// Mitsubishi GX Works2 project: 计数器   PLC: FX3U/FX3UC

PROGRAM MAIN
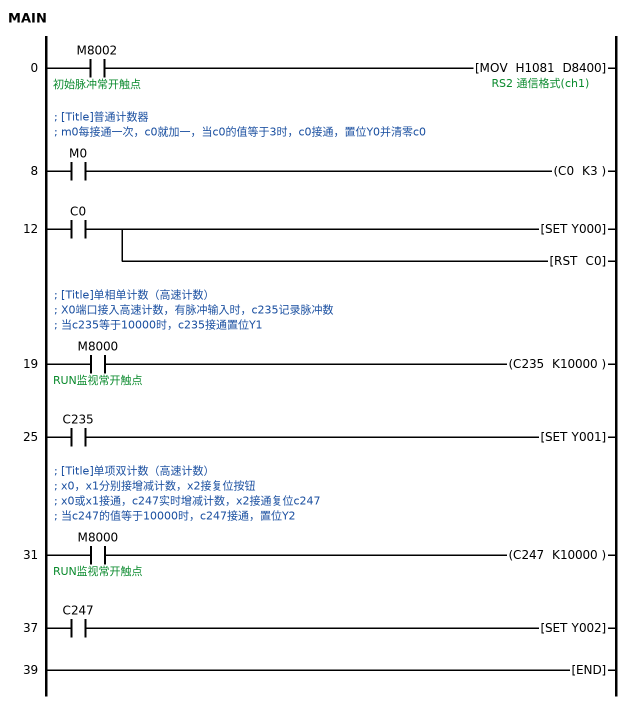
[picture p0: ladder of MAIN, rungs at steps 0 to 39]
0     LD      M8002  ; 初始脉冲常开触点
      MOV     H1081 D8400  ; RS2 通信格式(ch1)
; [Title]普通计数器
; m0每接通一次，c0就加一，当c0的值等于3时，c0接通，置位Y0并清零c0
8     LD      M0
      OUT     C0 K3
12    LD      C0
      SET     Y000
      RST     C0
; [Title]单相单计数（高速计数）
; X0端口接入高速计数，有脉冲输入时，c235记录脉冲数
; 当c235等于10000时，c235接通置位Y1
19    LD      M8000  ; RUN监视常开触点
      OUT     C235 K10000
25    LD      C235
      SET     Y001
; [Title]单项双计数（高速计数）
; x0，x1分别接增减计数，x2接复位按钮
; x0或x1接通，c247实时增减计数，x2接通复位c247
; 当c247的值等于10000时，c247接通，置位Y2
31    LD      M8000  ; RUN监视常开触点
      OUT     C247 K10000
37    LD      C247
      SET     Y002
39    END
END_PROGRAM

// device comments not shown above
C10  ; CCD1拍照连续不良计数
C11  ; CCD2连续不良计数
